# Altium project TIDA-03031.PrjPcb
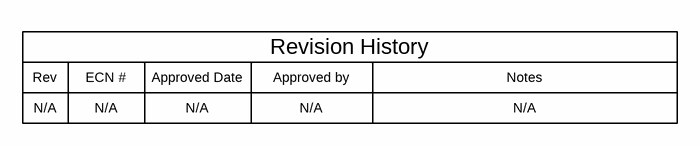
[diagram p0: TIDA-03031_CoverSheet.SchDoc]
TID: TIDA-03031; TechSupport: http://www.ti.com/support; SCH_Rev: E1; PRJ_Title: Input Protection and Backup Supply TI Design; PRJ_Number: TIDA-03031; PRJ_Engineer: Venkata Nandam; PRJ_Customer: Public Release; PCB_Rev: E1; PCB_Layout: Mansur; CopyrightYear: 2016
3 sheets, 64 parts. Net scope: global (net labels, ports and power ports of the same name join across sheets).
Board file: TIDA-03031.PcbDoc
Sheets:
  TIDA-03031_CoverSheet.SchDoc
  TIDA-03031.SchDoc
  TIDA-03031_Hardware.SchDoc

## Sheet TIDA-03031_CoverSheet.SchDoc
size 431 x 279 mm; Date: Not shown in title block; ApprovedBy: Not shown in title block; CheckedBy: Not shown in title block; Author: Not shown in title block; CompanyName: Not shown in title block; Engineer: Not shown in title block; Organization: Not shown in title block; Address1: Not shown in title block; Address2: Not shown in title block; Address3: Not shown in title block; Address4: Not shown in title block; DocumentNumber: 1; Revision: Use project parameter SCH_Rev; SheetNumber: 1; SheetTotal: 3; PageSetup: Record=PageOptions¦CenterHorizontal=True¦CenterVertical=True¦PrintScale=1.00¦XCorrection=1.00¦YCorrection=1.00¦PrintKind=0¦BorderSize=5000000¦LeftOffset=0¦BottomOffset=0¦Orientation=2¦PaperLength=1000¦PaperWidth=1000¦Scale=100¦PaperSource=15¦PrintQuality=600¦MediaType=1¦DitherType=10¦PaperKind=Letter¦PrintScaleMode=1; EVM_orderable: N/A

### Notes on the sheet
- Rev
- N/A
- ECN #
- Approved Date
- Approved by
- Revision History
- Notes

## Sheet TIDA-03031.SchDoc
size 431 x 279 mm; Date: Not shown in title block; ApprovedBy: Not shown in title block; CheckedBy: Not shown in title block; Author: Not shown in title block; CompanyName: Not shown in title block; Engineer: Not shown in title block; Organization: Not shown in title block; Address1: Not shown in title block; Address2: Not shown in title block; Address3: Not shown in title block; Address4: Not shown in title block; DocumentNumber: 1; Revision: Use project parameter SCH_Rev; SheetNumber: 2; SheetTotal: 3; PageSetup: Record=PageOptions¦CenterHorizontal=True¦CenterVertical=True¦PrintScale=0.62¦XCorrection=1.00¦YCorrection=1.00¦PrintKind=0¦BorderSize=5000000¦LeftOffset=0¦BottomOffset=0¦Orientation=2¦PaperLength=1000¦PaperWidth=1000¦Scale=100¦PaperSource=15¦PrintQuality=600¦MediaType=1¦DitherType=10¦PrintScaleMode=1¦PaperKind=Letter; EVM_orderable: N/A
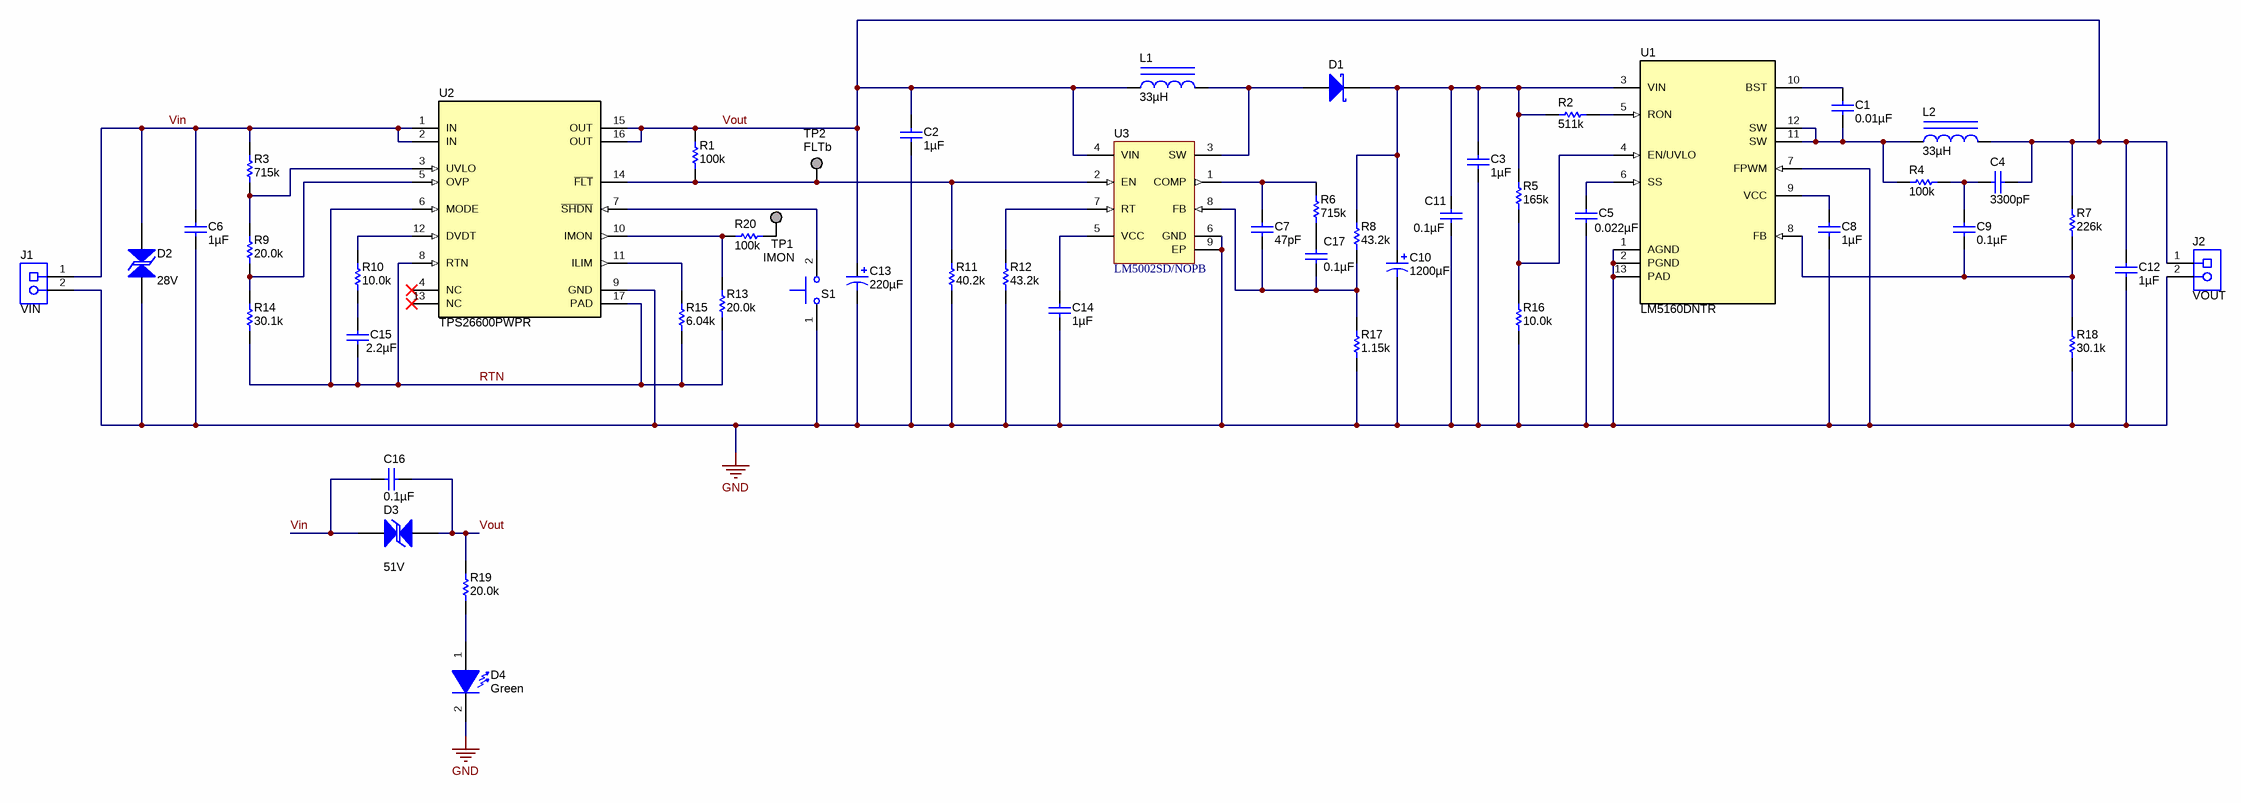
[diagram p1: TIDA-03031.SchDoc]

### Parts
C1  ValueDisplayed: 0.01µF  [0603]  (hidden comment: GRM188R72A103KA01D)
C2  ValueDisplayed: 1µF  [1206]  (hidden comment: GRM31MR71H105KA88L)
C3  ValueDisplayed: 1µF  [1206_180]  (hidden comment: GRM31CR72A105KA01L)
C4  ValueDisplayed: 3300pF  [0603]  (hidden comment: GRM188R72A332KA01D)
C5  ValueDisplayed: 0.022µF  [0603]  (hidden comment: GRM188R71C223KA01D)
C6  ValueDisplayed: 1µF  [1206_180]  (hidden comment: GRM31CR72A105KA01L)
C7  ValueDisplayed: 47pF  [0603]  (hidden comment: GRM1885C1H470JA01D)
C8  ValueDisplayed: 1µF  [0603]  (hidden comment: GRM188R71C105KA12D)
C9  ValueDisplayed: 0.1µF  [0603]  (hidden comment: GRM188R72A104KA35D)
C10  ValueDisplayed: 1200µF  [HE_1800x2500]  (hidden comment: UHE1H122MHD6)
C11  ValueDisplayed: 0.1µF  [0805_HV]  (hidden comment: GRM21BR72A104KAC4L)
C12  ValueDisplayed: 1µF  [1206]  (hidden comment: GRM31MR71H105KA88L)
C13  ValueDisplayed: 220µF  [UHE_1000x1250]  (hidden comment: UHE1V221MPD6)
C14  ValueDisplayed: 1µF  [0603]  (hidden comment: GRM188R71C105KA12D)
C15  ValueDisplayed: 2.2µF  [0805_HV]  (hidden comment: GRM219R71C225KE15)
C16  ValueDisplayed: 0.1µF  [0805_HV]  (hidden comment: GRM21BR72A104KAC4L)
C17  ValueDisplayed: 0.1µF  [0805_HV]  (hidden comment: GRM219R71C104KA01D)
D1  B160-13-F  [SMA]  (value not drawn)
D2  value 28V  [SMC]  (hidden comment: SMCJ28CA)
D3  value 51V  [SMA]  (hidden comment: SMAJ51CA)
D4  value Green  [LED_LTST-C190]  (hidden comment: LTST-C190GKT)
J1  VIN  [TEC_282841-2]
J2  VOUT  [TEC_282841-2]
L1  ValueDisplayed: 33µH  [LPS6235]  (hidden comment: LPS6235-333MLB)
L2  ValueDisplayed: 33µH  [LPS8045B]  (hidden comment: LPS8045B-333MRB)
R1  ValueDisplayed: 100k  [0603]  (hidden comment: CRCW0603100KFKEA)
R2  ValueDisplayed: 511k  [0603]  (hidden comment: CRCW0603511KFKEA)
R3  ValueDisplayed: 715k  [0603]  (hidden comment: CRCW0603715KFKEA)
R4  ValueDisplayed: 100k  [0603]  (hidden comment: CRCW0603100KFKEA)
R5  ValueDisplayed: 165k  [0603]  (hidden comment: CRCW0603165KFKEA)
R6  ValueDisplayed: 715k  [0603]  (hidden comment: CRCW0603715KFKEA)
R7  ValueDisplayed: 226k  [0603]  (hidden comment: CRCW0603226KFKEA)
R8  ValueDisplayed: 43.2k  [0603]  (hidden comment: CRCW060343K2FKEA)
R9  ValueDisplayed: 20.0k  [0603]  (hidden comment: CRCW060320K0FKEA)
R10  ValueDisplayed: 10.0k  [0603]  (hidden comment: CRCW060310K0FKEA)
R11  ValueDisplayed: 40.2k  [0603]  (hidden comment: CRCW060340K2FKEA)
R12  ValueDisplayed: 43.2k  [0603]  (hidden comment: CRCW060343K2FKEA)
R13  ValueDisplayed: 20.0k  [0603]  (hidden comment: CRCW060320K0FKEA)
R14  ValueDisplayed: 30.1k  [0603]  (hidden comment: CRCW060330K1FKEA)
R15  ValueDisplayed: 6.04k  [0603]  (hidden comment: CRCW06036K04FKEA)
R16  ValueDisplayed: 10.0k  [0603]  (hidden comment: CRCW060310K0FKEA)
R17  ValueDisplayed: 1.15k  [0603]  (hidden comment: CRCW06031K15FKEA)
R18  ValueDisplayed: 30.1k  [0603]  (hidden comment: CRCW060330K1FKEA)
R19  ValueDisplayed: 20.0k  [0603]  (hidden comment: CRCW060320K0FKEA)
R20  ValueDisplayed: 100k  [0603]  (hidden comment: CRCW0603100KFKEA)
S1  SKRKAEE010  [SW_SKRKAEE010]  (value not drawn)
TP1  IMON  [Keystone_5019]
TP2  FLTb  [Keystone_5019]
U1  LM5160DNTR  [DNT0012B]
U2  TPS26600PWPR  [PWP0016D_N]
U3  LM5002SD/NOPB  [SDC08A]

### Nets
GND: C2.2 C3.2 C5.2 C6.2 C8.1 C10.2(-) C11.1 C12.2 C13.2(-) C14.2 D2.1 D4.2(K) J1.2 J2.2 R11.1 R12.1 R16.1 R17.1 R18.1 S1.1 U1.1(AGND) U1.2(PGND) U1.7(FPWM) U1.13(PAD) U2.9(GND) U3.6(GND) U3.9(EP)
RTN: C15.2 R13.1 R14.1 R15.1 U2.6(MODE) U2.8(RTN) U2.17(PAD)
Vin: C6.1 C16.2 D2.2 D3.1 J1.1 R3.2 U2.1(IN) U2.2(IN)
Vout: C2.1 C4.1 C12.1 C13.1(+) C16.1 D3.2 J2.1 L1.1 L2.2 R1.2 R7.2 R19.2 U2.15(OUT) U2.16(OUT) U3.4(VIN)
NetC1_1: C1.1 L2.1 R4.2 U1.11(SW) U1.12(SW)
NetC1_2: C1.2 U1.10(BST)
NetC3_1: C3.1 C10.1(+) C11.2 D1.1(K) R2.1 R5.2 R8.2 U1.3(VIN)
NetC4_2: C4.2 C9.1 R4.1
NetC5_1: C5.1 U1.6(SS)
NetC7_1: C7.1 R6.1 U3.1(COMP)
NetC7_2: C7.2 C17.1 R8.1 R17.2 U3.8(FB)
NetC8_2: C8.2 U1.9(VCC)
NetC9_2: C9.2 R7.1 R18.2 U1.8(FB)
NetC14_1: C14.1 U3.5(VCC)
NetC15_1: C15.1 R10.1
NetC17_2: C17.2 R6.2
NetD1_2: D1.2(A) L1.2 U3.3(SW)
NetD4_1: D4.1(A) R19.1
NetR1_1: R1.1 R11.2 TP2.1 U2.14(~{FLT}) U3.2(EN)
NetR2_2: R2.2 U1.5(RON)
NetR3_1: R3.1 R9.2 U2.3(UVLO)
NetR5_1: R5.1 R16.2 U1.4(EN/UVLO)
NetR9_1: R9.1 R14.2 U2.5(OVP)
NetR10_2: R10.2 U2.12(DVDT)
NetR12_2: R12.2 U3.7(RT)
NetR13_2: R13.2 R20.1 U2.10(IMON)
NetR15_2: R15.2 U2.11(ILIM)
NetR20_2: R20.2 TP1.1
NetS1_2: S1.2 U2.7(~{SHDN})

Not connected (* = marked no-connect by the designer): U2 4(NC)* 13(NC)*

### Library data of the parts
C1 = GRM188R72A103KA01D: CAP, CERM, 0.01 µF, 100 V, +/- 10%, X7R, 0603; Manufacturer: MuRata; Polarized: N; CompType: Capacitor; Value: 0.01uF; U/M: EA; Cap_F: 0.00000001; Tolerance_%: 10; Value1: Unknown; VDC_V: 100; Value2: 100V; TaMin_C: -55; TaMax_C: 125; SizeArea_mm2: 1.28; SizeAreaWB_mm2: 4.68; SizeX_mm: 1.6; SizeY_mm: 0.8; SizeZ_mm: 1; AEC Category: Q200
C2 C12 = GRM31MR71H105KA88L: CAP, CERM, 1 µF, 50 V, +/- 10%, X7R, 1206; Manufacturer: MuRata; Polarized: N; CompType: Capacitor; Value: 1uF; U/M: EA; Cap_F: 0.000001; Tolerance_%: 10; Value1: Unknown; VDC_V: 50; Value2: 50V; TaMin_C: -55; TaMax_C: 125; SizeArea_mm2: 5.12; SizeAreaWB_mm2: 10.92; SizeX_mm: 3.2; SizeY_mm: 1.6; SizeZ_mm: 1.35; AEC Category: Q200
C3 C6 = GRM31CR72A105KA01L: CAP, CERM, 1 µF, 100 V, +/- 10%, X7R, 1206; Manufacturer: MuRata; Polarized: N; CompType: Capacitor; Value: 1uF; U/M: EA; Cap_F: 0.000001; Tolerance_%: 10; Value1: Unknown; VDC_V: 100; Value2: 100V; TaMin_C: -55; TaMax_C: 125; Cap_Case: 2220; SizeArea_mm2: 5.12; SizeAreaWB_mm2: 10.92; SizeX_mm: 3.2; SizeY_mm: 1.6; SizeZ_mm: 1.8; AEC Category: Q200
C4 = GRM188R72A332KA01D: CAP, CERM, 3300 pF, 100 V, +/- 10%, X7R, 0603; Manufacturer: MuRata; Polarized: N; CompType: Capacitor; Value: 3300pF; U/M: EA; Cap_F: 0.0000000033; Tolerance_%: 10; Value1: Unknown; VDC_V: 100; Value2: 100V; TaMin_C: -55; TaMax_C: 125; SizeArea_mm2: 1.28; SizeAreaWB_mm2: 4.68; SizeX_mm: 1.6; SizeY_mm: 0.8; SizeZ_mm: 1; AEC Category: Q200
C5 = GRM188R71C223KA01D: CAP, CERM, 0.022 µF, 16 V, +/- 10%, X7R, 0603; Manufacturer: MuRata; Polarized: N; CompType: Capacitor; Value: 0.022uF; U/M: EA; Cap_F: 0.000000022; Tolerance_%: 10; Value1: Unknown; VDC_V: 16; Value2: 16V; TaMin_C: -55; TaMax_C: 125; SizeArea_mm2: 1.28; SizeAreaWB_mm2: 4.68; SizeX_mm: 1.6; SizeY_mm: 0.8; SizeZ_mm: 1; AEC Category: Q200
C7 = GRM1885C1H470JA01D: CAP, CERM, 47 pF, 50 V, +/- 5%, C0G/NP0, 0603; Manufacturer: MuRata; Polarized: N; CompType: Capacitor; Value: 47pF; U/M: EA; Cap_F: 0.000000000047; Tolerance_%: 5; Value1: Unknown; VDC_V: 50; Value2: 50V; TaMin_C: -55; TaMax_C: 125; SizeArea_mm2: 1.28; SizeAreaWB_mm2: 4.68; SizeX_mm: 1.6; SizeY_mm: 0.8; SizeZ_mm: 1; AEC Category: Q200
C8 C14 = GRM188R71C105KA12D: CAP, CERM, 1 µF, 16 V, +/- 10%, X7R, 0603; Manufacturer: MuRata; Polarized: N; CompType: Capacitor; Value: 1uF; U/M: EA; Cap_F: 0.000001; Tolerance_%: 10; ESR_ohm: 0.011; Value1: 0.011 ohm; VDC_V: 16; Value2: 16V; TaMin_C: -55; TaMax_C: 125; SizeArea_mm2: 1.28; SizeAreaWB_mm2: 4.68; SizeX_mm: 1.6; SizeY_mm: 0.8; SizeZ_mm: 1; AEC Category: Q200
C9 = GRM188R72A104KA35D: CAP, CERM, 0.1 µF, 100 V, +/- 10%, X7R, 0603; Manufacturer: MuRata; Polarized: N; CompType: Capacitor; Value: 0.1uF; U/M: EA; Cap_F: 0.0000001; Tolerance_%: 10; Value1: Unknown; VDC_V: 100; Value2: 100V; TaMin_C: -55; TaMax_C: 125; SizeArea_mm2: 1.28; SizeAreaWB_mm2: 4.68; SizeX_mm: 1.6; SizeY_mm: 0.8; SizeZ_mm: 1; AEC Category: Q200
C10 = UHE1H122MHD6: CAP, AL, 1200 µF, 50 V, +/- 20%, TH; Manufacturer: Nichicon; Polarized: Y; CompType: Capacitor; Value: 1200uF; U/M: EA; Cap_F: 0.0012; Tolerance_%: 20; Value1: Unknown; VDC_V: 50; Value2: 50V; IRMS_A: 2.74; TaMin_C: -40; TaMax_C: 105; Cap_Case: 18x25mm; SizeAreaWB_mm2: 400; SizeArea_mm2: 324; SizeX_mm: 18; SizeZ_mm: 27; AEC Category: Q200; AEC Qualified: N
C11 C16 = GRM21BR72A104KAC4L: CAP, CERM, 0.1 µF, 100 V, +/- 10%, X7R, 0805; Manufacturer: MuRata; Polarized: N; CompType: Capacitor; Value: 0.1uF; U/M: EA; Cap_F: 0.0000001; Tolerance_%: 10; Value1: Unknown; VDC_V: 100; Value2: 100V; TaMin_C: -55; TaMax_C: 125; Cap_Case: 0805; SizeArea_mm2: 2.5; SizeAreaWB_mm2: 6.75; SizeX_mm: 2; SizeY_mm: 1.25; SizeZ_mm: 1.45; AEC Category: Q200
C13 = UHE1V221MPD6: CAP, AL, 220 µF, 35 V, +/- 20%, TH; Manufacturer: Nichicon; Polarized: Y; CompType: Capacitor; Value: 220uF; U/M: EA; Cap_F: 0.00022; Tolerance_%: 20; Value1: Unknown; VDC_V: 35; Value2: 35V; IRMS_A: 0.865; TaMin_C: -40; TaMax_C: 105; Cap_Case: 10x12.5; SizeAreaWB_mm2: 144; SizeArea_mm2: 100; SizeX_mm: 10; SizeZ_mm: 14; AEC Category: Q200; AEC Qualified: N
C15 = GRM219R71C225KE15: CAP, CERM, 2.2 µF, 16 V, +/- 10%, X7R, 0805; Manufacturer: MuRata; Polarized: N; CompType: Capacitor; Value: 2.2uF; U/M: EA; Cap_F: 0.0000022; Tolerance_%: 10; Value1: Unknown; VDC_V: 16; Value2: 16V; TaMin_C: -55; TaMax_C: 125; Cap_Case: 0805; SizeArea_mm2: 2.5; SizeAreaWB_mm2: 6.75; SizeX_mm: 2; SizeY_mm: 1.25; SizeZ_mm: 1.45; AEC Category: Q200
C17 = GRM219R71C104KA01D: CAP, CERM, 0.1 µF, 16 V, +/- 10%, X7R, 0805; Manufacturer: MuRata; Polarized: N; CompType: Capacitor; Value: 0.1uF; U/M: EA; Cap_F: 0.0000001; Tolerance_%: 10; Value1: Unknown; VDC_V: 16; Value2: 16V; TaMin_C: -55; TaMax_C: 125; Cap_Case: 0805; SizeArea_mm2: 2.5; SizeAreaWB_mm2: 6.75; SizeX_mm: 2; SizeY_mm: 1.25; SizeZ_mm: 1.45; AEC Category: Q200
D1 = B160-13-F: Diode, Schottky, 60 V, 1 A, SMA; Manufacturer: Diodes Inc.; U/M: EA; Vf_V: 0.7; Value: 60V; Value1: 1A; Value2: 0.7V; Io_A: 1; Vr_V: 60; TJmax_C: 150; RJC_CperW: 20; SizeAreaWB_mm2: 37.3428; SizeArea_mm2: 16.3228; SizeX_mm: 5.59; SizeY_mm: 2.92; SizeZ_mm: 2.87; AEC Category: Q101
D2 = SMCJ28CA: Diode, TVS, Bi, 28 V, 45.4 Vc, SMC; Manufacturer: Littelfuse; U/M: EA; Power_W: 6.5; Vr_V: 28; Value1: 6.5W; RJA_CperW: 75; SizeAreaWB_mm2: 83.2686; SizeArea_mm2: 50.5686; SizeX_mm: 8.13; SizeY_mm: 6.22; SizeZ_mm: 2.6; AEC Category: Q101; AEC Qualified: N
D3 = SMAJ51CA: Diode, TVS, Bi, 51 V, 400 W, SMA; Manufacturer: Littelfuse; U/M: EA; Power_W: 400; Vr_V: 51; Value1: 400W; RJA_CperW: 120; SizeAreaWB_mm2: 37.3428; SizeArea_mm2: 16.3228; SizeX_mm: 5.59; SizeY_mm: 2.92; SizeZ_mm: 2.87; AEC Category: Q101
D4 = LTST-C190GKT: LED, Green, SMD; Manufacturer: Lite-On; Vf_V: 2.1; Value2: 2.1V; Io_A: 0.02; Power_TotalModule: 0.1; Value1: 0.1W; U/M: EA
J1 J2 = 282841-2: Terminal Block, 2x1, 5.08mm, TH; Manufacturer: TE Connectivity; SymbolCreator: a0412235
L1 = LPS6235-333MLB: Inductor, Shielded Drum Core, Ferrite, 33 µH, 1.3 A, 0.18 ohm, SMD; Manufacturer: Coilcraft; Value: 33uH; Ind_H: 33.0E-6; Imax_A: 1.3; Irms: 1.3A @ 40C rise; Isat: 1.5A @ 30% inductance drop; DCR_ohm: 0.18; Value2: 1.3A; SizeAreaWB_mm2: 64; SizeArea_mm2: 36; SizeX_mm: 6; SizeZ_mm: 3.5; AEC Category: Q200
L2 = LPS8045B-333MRB: Inductor, Shielded, Ferrite, 33 µH, 1.2 A, 0.121 ohm, SMD; Manufacturer: Coilcraft; Value: 33uH; Ind_H: 33.0E-6; Imax_A: 1.2; Irms: 1.2A @ 20C rise; Isat: 1.8A @ 10% inductance drop; DCR_ohm: 0.121; Value2: 1.2A; AEC Category: Q200; AEC Qualified: N; SizeAreaWB_mm2: 101.525776; SizeArea_mm2: 65.221776; SizeX_mm: 8.076; SizeZ_mm: 4.7
R1 R4 R20 = CRCW0603100KFKEA: RES, 100 k, 1%, 0.1 W, 0603; Manufacturer: Vishay-Dale; CompType: Resistor; Value: 100k; Res_ohm: 100000; Tolerance_%: 1; Power_W: 0.1; Value2: 0.1W; VDC_V: 75; TempCo: 100 ppm/C; SizeArea_mm2: 1.28; SizeX_mm: 1.6; SizeY_mm: 0.8; EIA_Code: E96; U/M: EA; AEC Category: Q200
R2 = CRCW0603511KFKEA: RES, 511 k, 1%, 0.1 W, 0603; Manufacturer: Vishay-Dale; CompType: Resistor; Value: 511k; Res_ohm: 511000; Tolerance_%: 1; Power_W: 0.1; Value2: 0.1W; VDC_V: 75; TempCo: 100 ppm/C; SizeArea_mm2: 1.28; SizeX_mm: 1.6; SizeY_mm: 0.8; EIA_Code: E96; U/M: EA; AEC Category: Q200
R3 R6 = CRCW0603715KFKEA: RES, 715 k, 1%, 0.1 W, 0603; Manufacturer: Vishay-Dale; CompType: Resistor; Value: 715k; Res_ohm: 715000; Tolerance_%: 1; Power_W: 0.1; Value2: 0.1W; VDC_V: 75; TempCo: 100 ppm/C; SizeArea_mm2: 1.28; SizeX_mm: 1.6; SizeY_mm: 0.8; EIA_Code: E96; U/M: EA; AEC Category: Q200
R5 = CRCW0603165KFKEA: RES, 165 k, 1%, 0.1 W, 0603; Manufacturer: Vishay-Dale; CompType: Resistor; Value: 165k; Res_ohm: 165000; Tolerance_%: 1; Power_W: 0.1; Value2: 0.1W; VDC_V: 75; TempCo: 100 ppm/C; SizeArea_mm2: 1.28; SizeX_mm: 1.6; SizeY_mm: 0.8; EIA_Code: E96; U/M: EA; AEC Category: Q200
R7 = CRCW0603226KFKEA: RES, 226 k, 1%, 0.1 W, 0603; Manufacturer: Vishay-Dale; CompType: Resistor; Value: 226k; Res_ohm: 226000; Tolerance_%: 1; Power_W: 0.1; Value2: 0.1W; VDC_V: 75; TempCo: 100 ppm/C; SizeArea_mm2: 1.28; SizeX_mm: 1.6; SizeY_mm: 0.8; EIA_Code: E96; U/M: EA; AEC Category: Q200
R8 R12 = CRCW060343K2FKEA: RES, 43.2 k, 1%, 0.1 W, 0603; Manufacturer: Vishay-Dale; CompType: Resistor; Value: 43.2k; Res_ohm: 43200; Value_Code: 43k2; Tolerance_%: 1; Power_W: 0.1; Value2: 0.1W; VDC_V: 75; TempCo: 100 ppm/C; SizeArea_mm2: 1.28; SizeX_mm: 1.6; SizeY_mm: 0.8; EIA_Code: E96; U/M: EA; AEC Category: Q200
R9 R13 R19 = CRCW060320K0FKEA: RES, 20.0 k, 1%, 0.1 W, 0603; Manufacturer: Vishay-Dale; CompType: Resistor; Value: 20.0k; Res_ohm: 20000; Value_Code: 20k0; Tolerance_%: 1; Power_W: 0.1; Value2: 0.1W; VDC_V: 75; TempCo: 100 ppm/C; SizeArea_mm2: 1.28; SizeX_mm: 1.6; SizeY_mm: 0.8; EIA_Code: E96; U/M: EA; AEC Category: Q200
R10 R16 = CRCW060310K0FKEA: RES, 10.0 k, 1%, 0.1 W, 0603; Manufacturer: Vishay-Dale; CompType: Resistor; Value: 10.0k; Res_ohm: 10000; Value_Code: 10k0; Tolerance_%: 1; Power_W: 0.1; Value2: 0.1W; VDC_V: 75; TempCo: 100 ppm/C; SizeArea_mm2: 1.28; SizeX_mm: 1.6; SizeY_mm: 0.8; EIA_Code: E96; U/M: EA; AEC Category: Q200
R11 = CRCW060340K2FKEA: RES, 40.2 k, 1%, 0.1 W, 0603; Manufacturer: Vishay-Dale; CompType: Resistor; Value: 40.2k; Res_ohm: 40200; Value_Code: 40k2; Tolerance_%: 1; Power_W: 0.1; Value2: 0.1W; VDC_V: 75; TempCo: 100 ppm/C; SizeArea_mm2: 1.28; SizeX_mm: 1.6; SizeY_mm: 0.8; EIA_Code: E96; U/M: EA; AEC Category: Q200
R14 R18 = CRCW060330K1FKEA: RES, 30.1 k, 1%, 0.1 W, 0603; Manufacturer: Vishay-Dale; CompType: Resistor; Value: 30.1k; Res_ohm: 30100; Value_Code: 30k1; Tolerance_%: 1; Power_W: 0.1; Value2: 0.1W; VDC_V: 75; TempCo: 100 ppm/C; SizeArea_mm2: 1.28; SizeX_mm: 1.6; SizeY_mm: 0.8; EIA_Code: E96; U/M: EA; AEC Category: Q200
R15 = CRCW06036K04FKEA: RES, 6.04 k, 1%, 0.1 W, 0603; Manufacturer: Vishay-Dale; CompType: Resistor; Value: 6.04k; Res_ohm: 6040; Value_Code: 6k04; Tolerance_%: 1; Power_W: 0.1; Value2: 0.1W; VDC_V: 75; TempCo: 100 ppm/C; SizeArea_mm2: 1.28; SizeX_mm: 1.6; SizeY_mm: 0.8; EIA_Code: E96; U/M: EA; AEC Category: Q200
R17 = CRCW06031K15FKEA: RES, 1.15 k, 1%, 0.1 W, 0603; Manufacturer: Vishay-Dale; CompType: Resistor; Value: 1.15k; Res_ohm: 1150; Value_Code: 1k15; Tolerance_%: 1; Power_W: 0.1; Value2: 0.1W; VDC_V: 75; TempCo: 100 ppm/C; SizeArea_mm2: 1.28; SizeX_mm: 1.6; SizeY_mm: 0.8; EIA_Code: E96; U/M: EA; AEC Category: Q200
S1 = SKRKAEE010: Switch, Push Button, SMD; Manufacturer: Alps; SymbolCreator: a0412235; Circuit: SPST-NO; VDC_V: 12; SwitchFunction: Off-Mom; PositionCount: 1; CurrentRating_mA: 50
TP1 TP2 = 5019: Test Point, Miniature, SMT; Manufacturer: Keystone; CompType: Test Point Loop
U1 = LM5160DNTR: Wide Input 65V, 1.5A Synchronous Step-Down DC-DC Converter, DNT0012B; Alternate PartNumber: LM5160DNTT; Manufacturer: Texas Instruments; SymbolCreator: a0411947; SizeArea_mm2: 16; SizeAreaWB_mm2: 25; SizeX_mm: 4; SizeZ_mm: 0.8; CompType: IC; U/M: EA
U2 = TPS26600PWPR: 4.5V-55V, 0.15A-2A, 150mOhm Industrial eFuse, PWP0016D; Alternate PartNumber: TPS26600PWPT; Manufacturer: Texas Instruments; SymbolCreator: Altium; SizeArea_mm2: 32; SizeAreaWB_mm2: 58.8; SizeX_mm: 6.4; SizeY_mm: 5; SizeZ_mm: 1.2; CompType: IC; U/M: EA
U3 = LM5002SD/NOPB: High Voltage Switch Mode Regulator, 8-pin LLP, Pb-Free; Manufacturer: Texas Instruments; PackageTopMarking: NS*UZXYTT*LM5002; PowerWise: N; CompType: Switcher

## Sheet TIDA-03031_Hardware.SchDoc
size 431 x 279 mm; Date: Not shown in title block; ApprovedBy: Not shown in title block; CheckedBy: Not shown in title block; Author: Not shown in title block; CompanyName: Not shown in title block; Engineer: Not shown in title block; Organization: Not shown in title block; Address1: Not shown in title block; Address2: Not shown in title block; Address3: Not shown in title block; Address4: Not shown in title block; DocumentNumber: 1; Revision: Use project parameter SCH_Rev; SheetNumber: 3; SheetTotal: 3; PageSetup: Record=PageOptions¦CenterHorizontal=True¦CenterVertical=True¦PrintScale=1.00¦XCorrection=1.00¦YCorrection=1.00¦PrintKind=0¦BorderSize=5000000¦LeftOffset=0¦BottomOffset=0¦Orientation=2¦PaperLength=1000¦PaperWidth=1000¦Scale=100¦PaperSource=15¦PrintQuality=600¦MediaType=1¦DitherType=10¦PaperKind=Letter¦PrintScaleMode=1; EVM_orderable: N/A
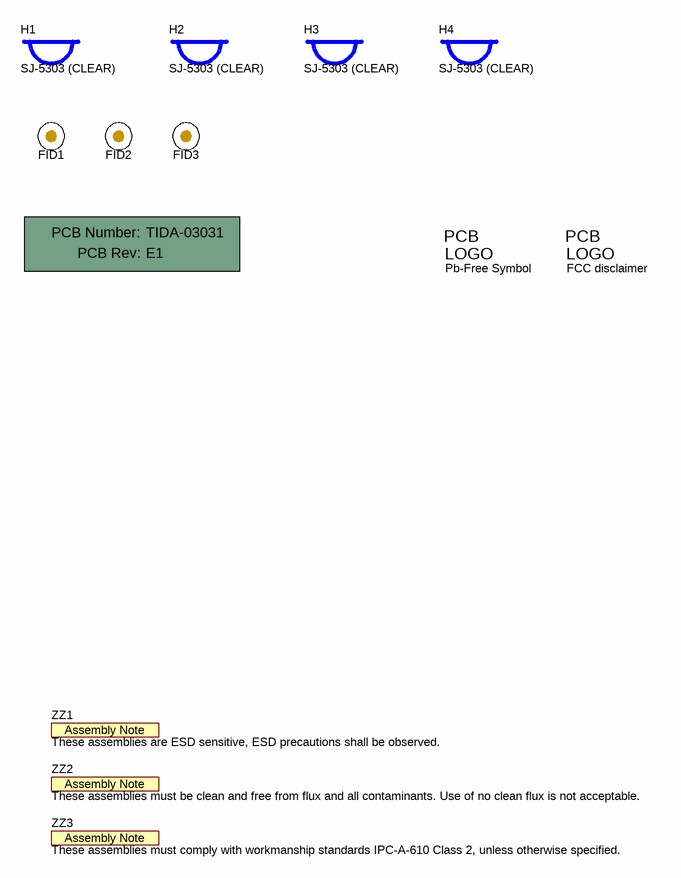
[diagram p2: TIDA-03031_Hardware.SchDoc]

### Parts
!PCB1  Printed Circuit Board  (value not drawn)  (mechanical)
FID1  Fiducial  [Fiducial10-20]  (value not drawn)
FID2  Fiducial  [Fiducial10-20]  (value not drawn)
FID3  Fiducial  [Fiducial10-20]  (value not drawn)
H1  SJ-5303 (CLEAR)  [Bumpon_SJ5003Transparent]
H2  SJ-5303 (CLEAR)  [Bumpon_SJ5003Transparent]
H3  SJ-5303 (CLEAR)  [Bumpon_SJ5003Transparent]
H4  SJ-5303 (CLEAR)  [Bumpon_SJ5003Transparent]
Logo2  Pb-Free Symbol  [Pb-Free_Overlay_Small]  (no BOM)
Logo3  FCC disclaimer  [FCC_disclaimer]  (no BOM)
ZZ1  These assemblies are ESD sensitive, ESD precautions shall be observed.  [AssemblyNote]  (no BOM)
ZZ2  These assemblies must be clean and free from flux and all contaminants. Use of no clean flux is not acceptable.  [AssemblyNote]  (no BOM)
ZZ3  These assemblies must comply with workmanship standards IPC-A-610 Class 2, unless otherwise specified.  [AssemblyNote]  (no BOM)

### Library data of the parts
!PCB1 = PCB: Manufacturer: Any; PartNumber: TIDA-03031; SymbolCreator: a0412235
FID1-FID3 = Fiducial: Fiducial mark.  There is nothing to buy or mount.; SymbolCreator: codlsc
H1-H4 = SJ-5303 (CLEAR): Bumpon, Hemisphere, 0.44 X 0.20, Clear; Manufacturer: 3M; SymbolCreator: a0412235
Logo2 = Pb-Free: SymbolCreator: a0412235
Logo3 = FCC_disclaimer: SymbolCreator: codlsc
ZZ1-ZZ3 = AssemblyNote: SymbolCreator: codlsc

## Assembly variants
001: not fitted C16 D3 FID1 FID2 FID3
